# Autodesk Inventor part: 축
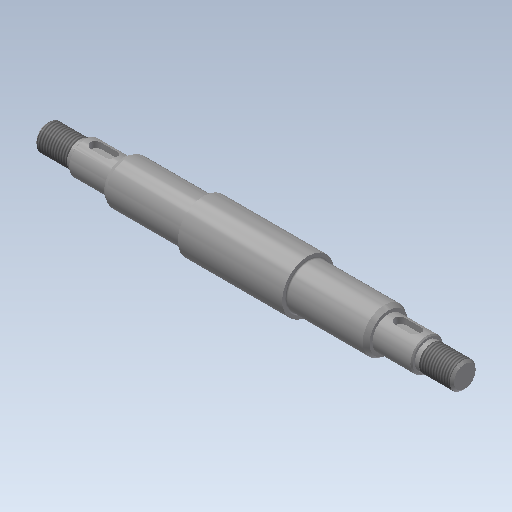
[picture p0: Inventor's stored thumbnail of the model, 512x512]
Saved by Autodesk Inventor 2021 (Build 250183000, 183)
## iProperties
Created: 2018-11
Part Number: 축
Material: 강철, 연강
Document SubType Name: Modeling
Designer: mduedu
Density: 1 g/cm^3
Appearance: 강철
Author: mduedu
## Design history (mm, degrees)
sketch "스케치1"
  geometry: L1 (-24, 0)-(24, 0); L2 (24, 0)-(24, 12); L3 (24, 12)-(-24, 12); L4 (-24, 12)-(-24, 0); L5 (-24, 0)-(-79, 0); L6 (-79, 0)-(-79, 7.5); L7 (-79, 7.5)-(-61, 7.5); L8 (-24, 7.5)-(-24, 0); L9 (-79, 0)-(-96, 0); L10 (-96, 0)-(-96, 6); L11 (-96, 6)-(-79, 6); L12 (-79, 6)-(-79, 0); L13 (0, 0)-(0, 12); L14 (24, 0)-(79, 0); L15 (79, 0)-(79, 7.5); L16 (79, 7.5)-(61, 7.5); L17 (24, 7.5)-(24, 0); L18 (79, 0)-(96, 0); L19 (96, 0)-(96, 6); L20 (96, 6)-(79, 6); L21 (79, 6)-(79, 0); L22 (-61, 7.5)-(-61, 8.85); L23 (-59.008, 10)-(-24, 10); L24 (24, 10)-(59.008, 10); L25 (61, 8.85)-(61, 7.5); L26 (-61, 8.85)-(-59.008, 10); L27 (61, 8.85)-(59.008, 10); 1 further point
  constraints: 54 end point, 9 parallel, 6 symmetric about line, 4 horizontal, 4 perpendicular, 2 midpoint, 2 point on line, 1 coincident
  dimensions: "d0" = 24 diameter of L3 L1; "d2" = 15 diameter of L7 L5; "d3" = 12 diameter of L11 L9; "d4" = 48 distance of L2.end L3.end; "d5" = 55 distance of L6.end L8.start; "d6" = 192 distance between parallel lines of L19 L10; "d24" = 20 diameter of L23 L5; "d25" = 18 distance of L6.end L7.end; "d26" = 18 distance of L15.end L16.end; "d27" = 20 diameter of L24 L14; "d28" = 55 distance between parallel lines of L15 L2; "d29" = 30 deg angle of L23 L26; "d30" = 17.7 diameter of L22.end L5; "d31" = 30 deg angle of L24 L27; "d32" = 17.7 diameter of L25.start L14
revolve "회전1" sketch "스케치1" stored, may be unused: angle "d7" = 90 deg
fillet "모깎기1" dims "d8" = 0.6
node "작업 평면1"
sketch "스케치2" dims "d11" = 12
  geometry: L1 (-3.5, 2.5)-(3.5, 2.5); L2 (3.5, 2.5)-(3.5, -2.5); L3 (3.5, -2.5)-(-3.5, -2.5); L4 (-3.5, -2.5)-(-3.5, 2.5); L5 (9, 7.5)-(9, -7.5) reference; 3 further points
  constraints: 8 end point, 2 midpoint, 2 parallel, 2 vertical alignment, 1 horizontal, 1 horizontal alignment, 1 perpendicular, 4 other
  dimensions: "d9" = 3 dimension on L5; "d10" = 5 distance between parallel lines of L3 L1
extrude "돌출1" cut sketch "스케치2" distance "d12" = 3; taper "d13" = 0 deg
chamfer "모따기1" distance "d14" = 0.5; stored, may be unused: second distance "d15" = 2, angle "d16" = 45 deg
feature "스레드1" dims "d17" = 15, "d18" = 0
feature "스레드2" dims "d19" = 15, "d20" = 0
chamfer "모따기2" distance "d21" = 1; stored, may be unused: second distance "d22" = 2, angle "d23" = 45 deg
node "솔리드1"
mirror "대칭1"
